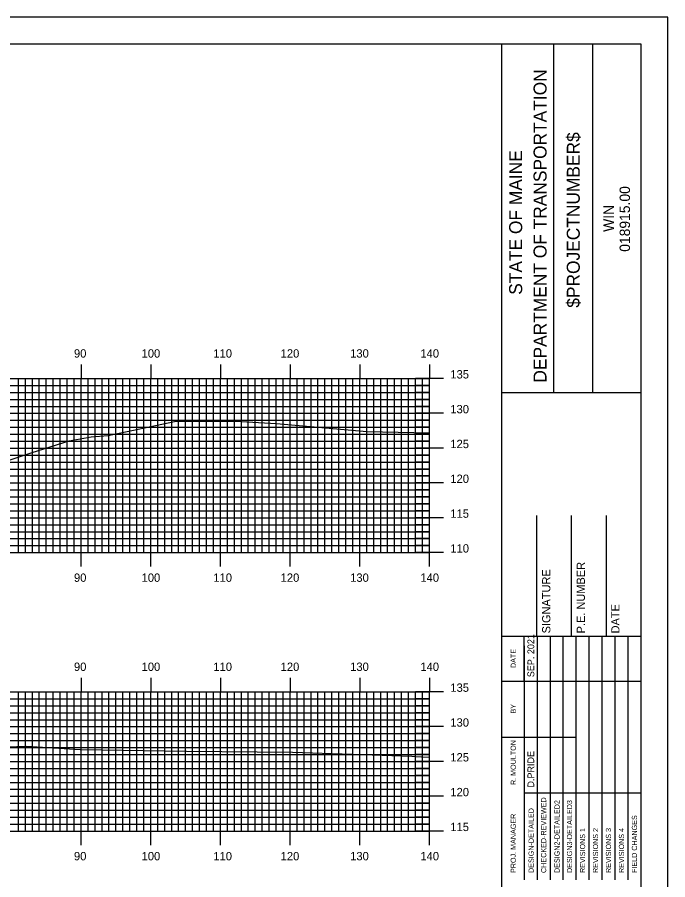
# Model space of a CAD drawing. Extents: x 842175 to 842518, y 363538 to 363758.
# Drawn here: x 842421.7 to 842515.1, y 363633.7 to 363757.6 of the extents above; entities that cross this region are included whole.
import ezdxf

# ---------------------------------------------------------------- set-up
doc = ezdxf.new("R2010")
doc.units = 0
for name, color, linetype in [('BORDER', 7, 'Continuous'), ('H_V ANNOTATION', 7, 'Continuous'), ('MAJOR', 7, 'Continuous'), ('MINOR', 7, 'Continuous'), ('PLOT BOUNDARY', 7, 'Continuous'), ('S_Roadway_Centerline', 7, 'Continuous')]:
    doc.layers.add(name, color=color, linetype=linetype)

msp = doc.modelspace()

# ---------------------------------------------------------------- linework, layer by layer
at = {"layer": 'BORDER'}
for p, q in [((842491.29, 363543.72), (842491.29, 363753.72)), ((842498.74, 363703.72), (842498.74, 363753.72)), ((842504.33, 363703.72), (842504.33, 363753.72)), ((842491.29, 363703.71), (842511.29, 363703.71)), ((842496.29, 363668.73), (842496.29, 363686.02)), ((842501.29, 363668.73), (842501.29, 363686.02)), ((842506.29, 363668.73), (842506.29, 363686.02)), ((842491.29, 363668.73), (842511.29, 363668.73))]:
    msp.add_line(p, q, dxfattribs=at)
msp.add_lwpolyline([(842191.29, 363543.72), (842511.29, 363543.72), (842511.29, 363753.72), (842191.29, 363753.72)], close=True, dxfattribs=at)
for points in [[(842494.51, 363662.23), (842494.51, 363668.73)], [(842496.38, 363633.73), (842496.38, 363668.73)], [(842498.24, 363668.73), (842498.24, 363633.73)], [(842500.11, 363633.73), (842500.11, 363668.73)], [(842501.97, 363633.73), (842501.97, 363668.73)], [(842503.83, 363633.73), (842503.83, 363668.73)], [(842505.7, 363633.73), (842505.7, 363668.73)], [(842507.56, 363633.73), (842507.56, 363668.73)], [(842509.42, 363633.73), (842509.42, 363668.73)], [(842494.52, 363633.73), (842494.52, 363667.31)], [(842491.29, 363662.23), (842511.29, 363662.23)], [(842491.29, 363654.23), (842494.52, 363654.23)], [(842494.51, 363654.23), (842501.97, 363654.23)], [(842494.51, 363646.23), (842511.29, 363646.23)]]:
    msp.add_lwpolyline(points, dxfattribs=at)
at = {"layer": 'MAJOR'}
for p, q in [((842430.89, 363707.73), (842430.89, 363705.72)), ((842440.89, 363707.73), (842440.89, 363705.72)), ((842450.89, 363707.73), (842450.89, 363705.72)), ((842460.89, 363707.73), (842460.89, 363705.72)), ((842470.89, 363707.73), (842470.89, 363705.72)), ((842480.89, 363707.73), (842480.89, 363705.72)), ((842200.89, 363705.72), (842480.89, 363705.72)), ((842200.89, 363705.72), (842480.89, 363705.72)), ((842430.89, 363680.72), (842430.89, 363705.72)), ((842440.89, 363680.72), (842440.89, 363705.72)), ((842450.89, 363680.72), (842450.89, 363705.72)), ((842460.89, 363680.72), (842460.89, 363705.72)), ((842470.89, 363680.72), (842470.89, 363705.72)), ((842482.89, 363705.72), (842478.88, 363705.72)), ((842480.89, 363680.72), (842480.89, 363705.72)), ((842480.89, 363680.72), (842480.89, 363705.72)), ((842200.89, 363700.72), (842480.89, 363700.72)), ((842482.89, 363700.72), (842478.88, 363700.72)), ((842200.89, 363695.72), (842480.89, 363695.72)), ((842482.89, 363695.72), (842478.88, 363695.72)), ((842200.89, 363690.72), (842480.89, 363690.72)), ((842482.89, 363690.72), (842478.88, 363690.72)), ((842200.89, 363685.72), (842480.89, 363685.72)), ((842482.89, 363685.72), (842478.88, 363685.72)), ((842200.89, 363680.72), (842480.89, 363680.72)), ((842200.89, 363680.72), (842480.89, 363680.72)), ((842430.89, 363678.72), (842430.89, 363680.72)), ((842440.89, 363678.72), (842440.89, 363680.72)), ((842450.89, 363678.72), (842450.89, 363680.72)), ((842460.89, 363678.72), (842460.89, 363680.72)), ((842470.89, 363678.72), (842470.89, 363680.72)), ((842482.89, 363680.72), (842478.88, 363680.72)), ((842480.89, 363678.72), (842480.89, 363680.72)), ((842430.89, 363662.73), (842430.89, 363660.72)), ((842440.89, 363662.73), (842440.89, 363660.72)), ((842450.89, 363662.73), (842450.89, 363660.72)), ((842460.89, 363662.73), (842460.89, 363660.72)), ((842470.89, 363662.73), (842470.89, 363660.72)), ((842480.89, 363662.73), (842480.89, 363660.72)), ((842200.89, 363660.72), (842480.89, 363660.72)), ((842200.89, 363660.72), (842480.89, 363660.72)), ((842430.89, 363640.72), (842430.89, 363660.72)), ((842440.89, 363640.72), (842440.89, 363660.72)), ((842450.89, 363640.72), (842450.89, 363660.72)), ((842460.89, 363640.72), (842460.89, 363660.72)), ((842470.89, 363640.72), (842470.89, 363660.72)), ((842482.89, 363660.72), (842478.88, 363660.72)), ((842480.89, 363640.72), (842480.89, 363660.72)), ((842480.89, 363640.72), (842480.89, 363660.72)), ((842200.89, 363655.72), (842480.89, 363655.72)), ((842482.89, 363655.72), (842478.88, 363655.72)), ((842200.89, 363650.72), (842480.89, 363650.72)), ((842482.89, 363650.72), (842478.88, 363650.72)), ((842200.89, 363645.72), (842480.89, 363645.72)), ((842482.89, 363645.72), (842478.88, 363645.72)), ((842200.89, 363640.72), (842480.89, 363640.72)), ((842200.89, 363640.72), (842480.89, 363640.72)), ((842430.89, 363638.72), (842430.89, 363640.72)), ((842440.89, 363638.72), (842440.89, 363640.72)), ((842450.89, 363638.72), (842450.89, 363640.72)), ((842460.89, 363638.72), (842460.89, 363640.72)), ((842470.89, 363638.72), (842470.89, 363640.72)), ((842482.89, 363640.72), (842478.88, 363640.72)), ((842480.89, 363638.72), (842480.89, 363640.72))]:
    msp.add_line(p, q, dxfattribs=at)
at = {"layer": 'MINOR'}
for p, q in [((842421.89, 363680.72), (842421.89, 363705.72)), ((842422.89, 363680.72), (842422.89, 363705.72)), ((842423.89, 363680.72), (842423.89, 363705.72)), ((842424.89, 363680.72), (842424.89, 363705.72)), ((842425.89, 363680.72), (842425.89, 363705.72)), ((842426.89, 363680.72), (842426.89, 363705.72)), ((842427.89, 363680.72), (842427.89, 363705.72)), ((842428.89, 363680.72), (842428.89, 363705.72)), ((842429.89, 363680.72), (842429.89, 363705.72)), ((842431.89, 363680.72), (842431.89, 363705.72)), ((842432.89, 363680.72), (842432.89, 363705.72)), ((842433.89, 363680.72), (842433.89, 363705.72)), ((842434.89, 363680.72), (842434.89, 363705.72)), ((842435.89, 363680.72), (842435.89, 363705.72)), ((842436.89, 363680.72), (842436.89, 363705.72)), ((842437.89, 363680.72), (842437.89, 363705.72)), ((842438.89, 363680.72), (842438.89, 363705.72)), ((842439.89, 363680.72), (842439.89, 363705.72)), ((842441.89, 363680.72), (842441.89, 363705.72)), ((842442.89, 363680.72), (842442.89, 363705.72)), ((842443.89, 363680.72), (842443.89, 363705.72)), ((842444.89, 363680.72), (842444.89, 363705.72)), ((842445.89, 363680.72), (842445.89, 363705.72)), ((842446.89, 363680.72), (842446.89, 363705.72)), ((842447.89, 363680.72), (842447.89, 363705.72)), ((842448.89, 363680.72), (842448.89, 363705.72)), ((842449.89, 363680.72), (842449.89, 363705.72)), ((842451.89, 363680.72), (842451.89, 363705.72)), ((842452.89, 363680.72), (842452.89, 363705.72)), ((842453.89, 363680.72), (842453.89, 363705.72)), ((842454.89, 363680.72), (842454.89, 363705.72)), ((842455.89, 363680.72), (842455.89, 363705.72)), ((842456.89, 363680.72), (842456.89, 363705.72)), ((842457.89, 363680.72), (842457.89, 363705.72)), ((842458.89, 363680.72), (842458.89, 363705.72)), ((842459.89, 363680.72), (842459.89, 363705.72)), ((842461.89, 363680.72), (842461.89, 363705.72)), ((842462.89, 363680.72), (842462.89, 363705.72)), ((842463.89, 363680.72), (842463.89, 363705.72)), ((842464.89, 363680.72), (842464.89, 363705.72)), ((842465.89, 363680.72), (842465.89, 363705.72)), ((842466.89, 363680.72), (842466.89, 363705.72)), ((842467.89, 363680.72), (842467.89, 363705.72)), ((842468.89, 363680.72), (842468.89, 363705.72)), ((842469.89, 363680.72), (842469.89, 363705.72)), ((842471.89, 363680.72), (842471.89, 363705.72)), ((842472.89, 363680.72), (842472.89, 363705.72)), ((842473.89, 363680.72), (842473.89, 363705.72)), ((842474.89, 363680.72), (842474.89, 363705.72)), ((842475.89, 363680.72), (842475.89, 363705.72)), ((842476.89, 363680.72), (842476.89, 363705.72)), ((842477.89, 363680.72), (842477.89, 363705.72)), ((842478.89, 363680.72), (842478.89, 363705.72)), ((842479.89, 363680.72), (842479.89, 363705.72)), ((842200.89, 363704.72), (842480.89, 363704.72)), ((842480.89, 363704.72), (842478.88, 363704.72)), ((842200.89, 363703.72), (842480.89, 363703.72)), ((842480.89, 363703.72), (842478.88, 363703.72)), ((842200.89, 363702.72), (842480.89, 363702.72)), ((842480.89, 363702.72), (842478.88, 363702.72)), ((842200.89, 363701.72), (842480.89, 363701.72)), ((842480.89, 363701.72), (842478.88, 363701.72)), ((842200.89, 363699.72), (842480.89, 363699.72)), ((842480.89, 363699.72), (842478.88, 363699.72)), ((842200.89, 363698.72), (842480.89, 363698.72)), ((842480.89, 363698.72), (842478.88, 363698.72)), ((842200.89, 363697.72), (842480.89, 363697.72)), ((842480.89, 363697.72), (842478.88, 363697.72)), ((842200.89, 363696.72), (842480.89, 363696.72)), ((842480.89, 363696.72), (842478.88, 363696.72)), ((842200.89, 363694.72), (842480.89, 363694.72)), ((842480.89, 363694.72), (842478.88, 363694.72)), ((842200.89, 363693.72), (842480.89, 363693.72)), ((842480.89, 363693.72), (842478.88, 363693.72)), ((842200.89, 363692.72), (842480.89, 363692.72)), ((842480.89, 363692.72), (842478.88, 363692.72)), ((842200.89, 363691.72), (842480.89, 363691.72)), ((842480.89, 363691.72), (842478.88, 363691.72)), ((842200.89, 363689.72), (842480.89, 363689.72)), ((842480.89, 363689.72), (842478.88, 363689.72)), ((842200.89, 363688.72), (842480.89, 363688.72)), ((842480.89, 363688.72), (842478.88, 363688.72)), ((842200.89, 363687.72), (842480.89, 363687.72)), ((842480.89, 363687.72), (842478.88, 363687.72)), ((842200.89, 363686.72), (842480.89, 363686.72)), ((842480.89, 363686.72), (842478.88, 363686.72)), ((842200.89, 363684.72), (842480.89, 363684.72)), ((842480.89, 363684.72), (842478.88, 363684.72)), ((842200.89, 363683.72), (842480.89, 363683.72)), ((842480.89, 363683.72), (842478.88, 363683.72)), ((842200.89, 363682.72), (842480.89, 363682.72)), ((842480.89, 363682.72), (842478.88, 363682.72)), ((842200.89, 363681.72), (842480.89, 363681.72)), ((842480.89, 363681.72), (842478.88, 363681.72)), ((842200.89, 363659.72), (842480.89, 363659.72)), ((842421.89, 363640.72), (842421.89, 363660.72)), ((842422.89, 363640.72), (842422.89, 363660.72)), ((842423.89, 363640.72), (842423.89, 363660.72)), ((842424.89, 363640.72), (842424.89, 363660.72)), ((842425.89, 363640.72), (842425.89, 363660.72)), ((842426.89, 363640.72), (842426.89, 363660.72)), ((842427.89, 363640.72), (842427.89, 363660.72)), ((842428.89, 363640.72), (842428.89, 363660.72)), ((842429.89, 363640.72), (842429.89, 363660.72)), ((842431.89, 363640.72), (842431.89, 363660.72)), ((842432.89, 363640.72), (842432.89, 363660.72)), ((842433.89, 363640.72), (842433.89, 363660.72)), ((842434.89, 363640.72), (842434.89, 363660.72)), ((842435.89, 363640.72), (842435.89, 363660.72)), ((842436.89, 363640.72), (842436.89, 363660.72)), ((842437.89, 363640.72), (842437.89, 363660.72)), ((842438.89, 363640.72), (842438.89, 363660.72)), ((842439.89, 363640.72), (842439.89, 363660.72)), ((842441.89, 363640.72), (842441.89, 363660.72)), ((842442.89, 363640.72), (842442.89, 363660.72)), ((842443.89, 363640.72), (842443.89, 363660.72)), ((842444.89, 363640.72), (842444.89, 363660.72)), ((842445.89, 363640.72), (842445.89, 363660.72)), ((842446.89, 363640.72), (842446.89, 363660.72)), ((842447.89, 363640.72), (842447.89, 363660.72)), ((842448.89, 363640.72), (842448.89, 363660.72)), ((842449.89, 363640.72), (842449.89, 363660.72)), ((842451.89, 363640.72), (842451.89, 363660.72)), ((842452.89, 363640.72), (842452.89, 363660.72)), ((842453.89, 363640.72), (842453.89, 363660.72)), ((842454.89, 363640.72), (842454.89, 363660.72)), ((842455.89, 363640.72), (842455.89, 363660.72)), ((842456.89, 363640.72), (842456.89, 363660.72)), ((842457.89, 363640.72), (842457.89, 363660.72)), ((842458.89, 363640.72), (842458.89, 363660.72)), ((842459.89, 363640.72), (842459.89, 363660.72)), ((842461.89, 363640.72), (842461.89, 363660.72)), ((842462.89, 363640.72), (842462.89, 363660.72)), ((842463.89, 363640.72), (842463.89, 363660.72)), ((842464.89, 363640.72), (842464.89, 363660.72)), ((842465.89, 363640.72), (842465.89, 363660.72)), ((842466.89, 363640.72), (842466.89, 363660.72)), ((842467.89, 363640.72), (842467.89, 363660.72)), ((842468.89, 363640.72), (842468.89, 363660.72)), ((842469.89, 363640.72), (842469.89, 363660.72)), ((842471.89, 363640.72), (842471.89, 363660.72)), ((842472.89, 363640.72), (842472.89, 363660.72)), ((842473.89, 363640.72), (842473.89, 363660.72)), ((842474.89, 363640.72), (842474.89, 363660.72)), ((842475.89, 363640.72), (842475.89, 363660.72)), ((842476.89, 363640.72), (842476.89, 363660.72)), ((842477.89, 363640.72), (842477.89, 363660.72)), ((842480.89, 363659.72), (842478.88, 363659.72)), ((842478.89, 363640.72), (842478.89, 363660.72)), ((842479.89, 363640.72), (842479.89, 363660.72)), ((842200.89, 363658.72), (842480.89, 363658.72)), ((842480.89, 363658.72), (842478.88, 363658.72)), ((842200.89, 363657.72), (842480.89, 363657.72)), ((842480.89, 363657.72), (842478.88, 363657.72)), ((842200.89, 363656.72), (842480.89, 363656.72)), ((842480.89, 363656.72), (842478.88, 363656.72)), ((842200.89, 363654.72), (842480.89, 363654.72)), ((842480.89, 363654.72), (842478.88, 363654.72)), ((842200.89, 363653.72), (842480.89, 363653.72)), ((842480.89, 363653.72), (842478.88, 363653.72)), ((842200.89, 363652.72), (842480.89, 363652.72)), ((842480.89, 363652.72), (842478.88, 363652.72)), ((842200.89, 363651.72), (842480.89, 363651.72)), ((842480.89, 363651.72), (842478.88, 363651.72)), ((842200.89, 363649.72), (842480.89, 363649.72)), ((842480.89, 363649.72), (842478.88, 363649.72)), ((842200.89, 363648.72), (842480.89, 363648.72)), ((842480.89, 363648.72), (842478.88, 363648.72)), ((842200.89, 363647.72), (842480.89, 363647.72)), ((842480.89, 363647.72), (842478.88, 363647.72)), ((842200.89, 363646.72), (842480.89, 363646.72)), ((842480.89, 363646.72), (842478.88, 363646.72)), ((842200.89, 363644.72), (842480.89, 363644.72)), ((842200.89, 363643.72), (842480.89, 363643.72)), ((842480.89, 363644.72), (842478.88, 363644.72)), ((842480.89, 363643.72), (842478.88, 363643.72)), ((842200.89, 363642.72), (842480.89, 363642.72)), ((842480.89, 363642.72), (842478.88, 363642.72)), ((842200.89, 363641.72), (842480.89, 363641.72)), ((842480.89, 363641.72), (842478.88, 363641.72))]:
    msp.add_line(p, q, dxfattribs=at)
at = {"layer": 'PLOT BOUNDARY'}
msp.add_lwpolyline([(842175.1, 363537.6), (842515.1, 363537.6), (842515.1, 363757.6), (842175.1, 363757.6)], close=True, dxfattribs=at)
at = {"layer": 'S_Roadway_Centerline'}
for points in [[(842414.63, 363692.04), (842423.86, 363695.09), (842429.19, 363696.78), (842432.34, 363697.33), (842434.77, 363697.54), (842444.3, 363699.56), (842452.94, 363699.6), (842458.92, 363699.24), (842471.9, 363698.1), (842480.89, 363697.92)], [(842418.83, 363652.76), (842423.03, 363652.9), (842430.73, 363652.44), (842446.02, 363652.2), (842461.23, 363652.03), (842478.34, 363651.47), (842478.93, 363651.43), (842479.76, 363651.39), (842480.89, 363651.33)]]:
    msp.add_lwpolyline(points, dxfattribs=at)

# ---------------------------------------------------------------- texts
at = {"layer": 'BORDER'}
for s, height, p in [('DEPARTMENT OF TRANSPORTATION', 1.8635, (842497.7, 363705.13)), ('$PROJECTNUMBER$', 1.8635, (842502.47, 363715.88)), ('STATE OF MAINE', 1.8635, (842494.2, 363717.74)), ('018915.00', 1.491, (842509.68, 363723.92)), ('WIN', 1.491, (842507.36, 363726.78)), ('SIGNATURE', 1.181, (842498.25, 363669.11)), ('P.E. NUMBER', 1.1811, (842503.21, 363669.11)), ('DATE', 1.181, (842508.17, 363669.11)), ('SEP. 2021', 0.969, (842495.93, 363662.82)), ('DATE', 0.743, (842493.29, 363664.14)), ('BY', 0.743, (842493.29, 363657.6)), ('R. MOULTON', 0.745, (842493.29, 363647.33)), ('D.PRIDE', 0.969, (842495.93, 363646.97)), ('CHECKED-REVIEWED', 0.7455, (842497.65, 363634.7)), ('DESIGN2-DETAILED2', 0.7455, (842499.58, 363634.7)), ('DESIGN3-DETAILED3', 0.7455, (842501.37, 363634.7)), ('DESIGN-DETAILED', 0.7455, (842495.86, 363634.7)), ('PROJ. MANAGER', 0.7455, (842493.29, 363634.7)), ('FIELD CHANGES', 0.7455, (842510.69, 363634.7)), ('REVISIONS 1', 0.7455, (842503.24, 363634.7)), ('REVISIONS 2', 0.7455, (842505.1, 363634.7)), ('REVISIONS 3', 0.7455, (842506.96, 363634.7)), ('REVISIONS 4', 0.7455, (842508.83, 363634.7))]:
    msp.add_text(s, height=height, rotation=90, dxfattribs=at).set_placement(p)
at = {"layer": 'H_V ANNOTATION'}
for s, p in [('90', (842429.86, 363708.72)), ('100', (842439.57, 363708.72)), ('110', (842449.87, 363708.72)), ('120', (842459.53, 363708.72)), ('130', (842469.51, 363708.72)), ('140', (842479.59, 363708.72)), ('135', (842483.89, 363705.72)), ('130', (842483.89, 363700.72)), ('125', (842483.89, 363695.72)), ('120', (842483.89, 363690.72)), ('115', (842483.89, 363685.72)), ('110', (842483.89, 363680.72)), ('90', (842429.86, 363676.52)), ('100', (842439.57, 363676.52)), ('110', (842449.87, 363676.52)), ('120', (842459.53, 363676.52)), ('130', (842469.51, 363676.52)), ('140', (842479.59, 363676.52)), ('90', (842429.86, 363663.72)), ('100', (842439.57, 363663.72)), ('110', (842449.87, 363663.72)), ('120', (842459.53, 363663.72)), ('130', (842469.51, 363663.72)), ('140', (842479.59, 363663.72)), ('135', (842483.89, 363660.72)), ('130', (842483.89, 363655.72)), ('125', (842483.89, 363650.72)), ('120', (842483.89, 363645.72)), ('115', (842483.89, 363640.72)), ('90', (842429.86, 363636.52)), ('100', (842439.57, 363636.52)), ('110', (842449.87, 363636.52)), ('120', (842459.53, 363636.52)), ('130', (842469.51, 363636.52)), ('140', (842479.59, 363636.52))]:
    msp.add_text(s, height=1.2, dxfattribs=at).set_placement(p)

doc.saveas('drawing.dxf')
